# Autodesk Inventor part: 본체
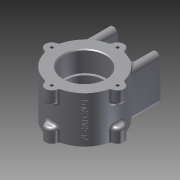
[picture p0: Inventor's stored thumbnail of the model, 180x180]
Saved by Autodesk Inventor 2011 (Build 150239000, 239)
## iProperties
Created: 2015-03
Part Number: 본체
Document SubType Name: Modeling
Designer: LINEART07
Density: 1 g/cm^3
Author: LINEART07
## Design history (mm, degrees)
sketch "스케치5"
  geometry: C1 r 37 at (0, 0); 1 further point
  constraints: 1 centre point, 1 coincident
  dimensions: "d17" = 74 diameter of C1
extrude "돌출4" new body sketch "스케치5" distance "d18" = 52; taper "d19" = 0 deg
sketch "스케치6"
  geometry: A1 r 37 centre (0, 0) between (-6.969, 36.338) and (6.969, 36.338) reference; A2 r 7 centre (0, 37) between (6.969, 36.338) and (-6.969, 36.338)
  constraints: 4 point on circle, 1 centre point
  dimensions: "d20" = 7 radius of A2
extrude "돌출5" join sketch "스케치6" distance "d21" = 15; taper "d22" = 0 deg
sketch "스케치7"
  geometry: A1 r 7 centre (0, 37) between (6.969, 36.338) and (-6.969, 36.338) reference; A2 r 37 centre (0, 0) between (6.969, 36.338) and (-6.969, 36.338) reference; A3 r 7 centre (0, 37) between (6.969, 36.338) and (-6.969, 36.338)
  constraints: 4 point on circle, 1 centre point, 1 coincident
extrude "돌출6" join sketch "스케치7" distance "d26" = 15; taper "d27" = 0 deg
node "작업 평면2"
sketch "스케치8"
  geometry: L1 (-36.338, 52)-(-6.969, 52) reference; L2 (7, 52)-(-7, 52) reference; L3 (-7, 0)-(7, 0) reference; L4 (0, 0)-(0, 52); L5 (-24, 58.838)-(-24, -13.337); L6 (-55.49, 46)-(59.857, 46); L7 (-59.657, 6)-(61.023, 6); L8 (0, 26)-(-59.491, 26) reference; L9 (-29, 46)-(-29, 6); L10 (-19, 6)-(-19, 46); A1 r 5 centre (-24, 46) between (-19, 46) and (-29, 46); A2 r 5 centre (-24, 6) between (-29, 6) and (-19, 6); 3 further points
  constraints: 14 end point, 8 point on line, 4 point on circle, 3 parallel, 2 centre point, 2 midpoint, 2 perpendicular, 1 horizontal
  dimensions: "d32" = 24 distance between parallel lines of L4 L5; "d33" = 20 distance between parallel lines of L7 L8; "d34" = 20 distance between parallel lines of L6 L8
extrude "돌출7" join sketch "스케치8" stored distance "d35" = 15; taper "d36" = 0 deg
sketch "스케치9"
  geometry: L1 (-6.969, 15)-(6.969, 15) reference; L2 (6.969, 0)-(6.969, 15) reference; L3 (-6.969, 0)-(6.969, 0) reference; L4 (-6.969, 15)-(-6.969, 0) reference; L5 (31.749, 6)-(31.749, 46) reference; L6 (22.978, 46)-(22.978, 6) reference; L7 (31.749, 46)-(31.749, 6) reference; L8 (22.978, 6)-(22.978, 46) reference; L9 (6.969, 52)-(6.969, 37) reference; L10 (6.969, 37)-(-6.969, 37) reference; L11 (-6.969, 37)-(-6.969, 52) reference; L12 (-6.969, 52)-(-36.338, 52) reference; L13 (-36.338, 52)-(-36.338, 37) reference; L14 (-36.338, 37)-(-36.338, 37) reference; L15 (-36.338, 37)-(-36.338, 52) reference; L16 (-36.338, 52)-(-6.969, 52) reference; L17 (-6.969, 52)-(-6.969, 37) reference; L18 (-6.969, 37)-(6.969, 37) reference; L19 (6.969, 37)-(6.969, 52) reference; L20 (6.969, 52)-(36.338, 52) reference; L21 (36.338, 52)-(36.338, 37) reference; L22 (36.338, 37)-(36.338, 37) reference; L23 (36.338, 37)-(36.338, 52) reference; L24 (36.338, 52)-(6.969, 52) reference; L25 (-6.969, 0)-(-6.969, 15) reference; L26 (-6.969, 15)-(6.969, 15) reference; L27 (6.969, 15)-(6.969, 0) reference; L28 (36.338, 0)-(6.969, 0) reference; L29 (36.338, 0)-(36.338, 15) reference; L30 (36.338, 15)-(36.338, 15) reference; L31 (36.338, 15)-(36.338, 0) reference; L32 (6.969, 0)-(36.338, 0) reference; L33 (6.969, 0)-(6.969, 15) reference; L34 (6.969, 15)-(-6.969, 15) reference; L35 (-6.969, 15)-(-6.969, 0) reference; L36 (-36.338, 0)-(-6.969, 0) reference; L37 (-36.338, 0)-(-36.338, 15) reference; L38 (-36.338, 15)-(-36.338, 15) reference; L39 (-36.338, 15)-(-36.338, 0) reference; L40 (-6.969, 0)-(-36.338, 0) reference; L41 (6.969, 37)-(-6.969, 37) reference; L42 (-6.969, 52)-(-6.969, 37) reference; L43 (6.969, 52)-(-6.969, 52) reference; L44 (6.969, 37)-(6.969, 52) reference; L45 (0, -9.9)-(0, 64.335) reference; L46 (0, 0)-(-23.5, 0); L47 (-23.5, 0)-(-23.5, 23.5); L48 (-23.5, 23.5)-(0, 23.5); L49 (0, 23.5)-(0, 0); L50 (0, 52)-(-23.5, 52); L51 (-23.5, 52)-(-23.5, 28.5); L52 (-23.5, 28.5)-(0, 28.5); L53 (0, 28.5)-(0, 52); L54 (0, 23.5)-(-21, 23.5); L55 (-21, 23.5)-(-21, 28.5); L56 (-21, 28.5)-(0, 28.5); L57 (0, 28.5)-(0, 23.5)
  constraints: 26 end point, 7 parallel, 4 horizontal alignment, 3 horizontal, 3 perpendicular, 2 point on line, 1 midpoint, 1 vertical
  dimensions: "d82" = 23.5 distance between parallel lines of L45 L47; "d83" = 23.5 distance between parallel lines of L53 L51
revolve "회전1" sketch "스케치9" stored, may be unused: angle "d37" = 90 deg
sketch "스케치10"
  geometry: A1 r 7 centre (-37, 0) between (-36.338, 6.969) and (-36.338, -6.969) reference; 1 further point
  constraints: 1 coincident
hole "Hole1" sketch "스케치10" at (-37, 0) diameter "d38" = 3.242; stored, may be unused: countersink angle "d42" = 90 deg, drill point angle "d44" = 118 deg; dims "d39" = 8, "d40" = 4, "d41" = 2, "d43" = 11
sketch "스케치11"
  geometry: A1 r 7 centre (0, -37) between (-6.969, -36.338) and (6.969, -36.338) reference; 1 further point
  constraints: 1 coincident
hole "Hole2" sketch "스케치11" at (0, -37) diameter "d48" = 3.242; stored, may be unused: countersink angle "d52" = 90 deg, drill point angle "d54" = 118 deg; dims "d49" = 8, "d50" = 4, "d51" = 2, "d53" = 11
sketch "스케치12"
  geometry: A1 r 5 centre (24, -6) between (29, -6) and (19, -6) reference; A2 r 5 centre (24, -46) between (19, -46) and (29, -46) reference; 3 further points
  constraints: 2 coincident
hole "Hole4" sketch "스케치12" at (24, -6), (24, -46) diameter "d65" = 4.134; stored, may be unused: countersink angle "d69" = 90 deg, drill point angle "d71" = 118 deg; dims "d66" = 6, "d67" = 4, "d68" = 2, "d70" = 8
fillet "모깎기1" dims "d72" = 0.3
fillet "모깎기2" dims "d73" = 3
fillet "모깎기3" dims "d74" = 3
chamfer "모따기1" distance "d75" = 1; stored, may be unused: second distance "d76" = 2, angle "d77" = 45 deg
node "작업 평면6"
  node "작업 평면5"
sketch "스케치15"
  geometry: L1 (36.628, 46)-(36.628, 6) reference; L2 (36.976, 52)-(31.796, 52) reference; L3 (31.796, 40)-(31.796, 52) reference; L4 (24.303, 34)-(27.899, 34) reference; L5 (18.921, 52)-(18.921, 40) reference; L6 (18.921, 52)-(-18.921, 52) reference; L7 (-18.921, 40)-(-18.921, 52) reference; L8 (-27.899, 34)-(-24.303, 34) reference; L9 (-31.796, 52)-(-31.796, 40) reference; L10 (-31.796, 52)-(-31.796, 52) reference; L11 (-31.796, 40)-(-31.796, 52) reference; L12 (-24.303, 34)-(-27.899, 34) reference; L13 (-18.921, 52)-(-18.921, 40) reference; L14 (-18.921, 52)-(-1.342, 52) reference; L15 (-5.233, 6)-(-5.233, 46) reference; L16 (-18.921, 0)-(-1.342, 0) reference; L17 (-18.921, 12)-(-18.921, 0) reference; L18 (-27.899, 18)-(-24.303, 18) reference; L19 (-31.796, 0)-(-31.796, 12) reference; L20 (-31.796, 0)-(-31.796, 0) reference; L21 (-31.796, 12)-(-31.796, 0) reference; L22 (-24.303, 18)-(-27.899, 18) reference; L23 (-18.921, 0)-(-18.921, 12) reference; L24 (18.921, 0)-(-18.921, 0) reference; L25 (18.921, 12)-(18.921, 0) reference; L26 (27.899, 18)-(24.303, 18) reference; L27 (31.796, 0)-(31.796, 12) reference; L28 (36.976, 0)-(31.796, 0) reference; L29 (-37, 0)-(-37, 52) reference; L30 (0, 0)-(0, 52); 4 further points
  constraints: 3 midpoint, 2 end point, 1 coincident, 1 horizontal alignment, 1 parallel, 1 vertical alignment, 17 other
  node "투영된 루프5"
sketch "스케치16"
  geometry: 1 further point
feature "엠보싱1" dims "d26" = 15, "d80" = 0.5, "d81" = 0
node "솔리드2"
pattern_circular "원형 패턴2" dims angle "d24" = 360 deg
pattern_circular "원형 패턴3" dims angle "d29" = 360 deg
mirror "대칭1"
pattern_circular "원형 패턴4" dims angle "d46" = 360 deg
pattern_circular "원형 패턴5" dims angle "d56" = 360 deg
mirror "대칭2"
node "투영된 루프1"
node "투영된 루프2"
node "투영된 루프3"
node "투영된 루프4"
node "작업축1"
other parameters: "d31" = 56, "d78" = 45 deg
